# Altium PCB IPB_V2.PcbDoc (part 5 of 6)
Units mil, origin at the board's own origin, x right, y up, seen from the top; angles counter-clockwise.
Board outline 14000 x 12000 mil, 6 copper layers (Top, L2 - Plane/Horiz, L3 - Horiz, L4 - Vert, L5 - Plane/Horiz, Bottom), stack 61.468 mil thick; 657 components, 436 nets, 1897 pads, 873 vias.
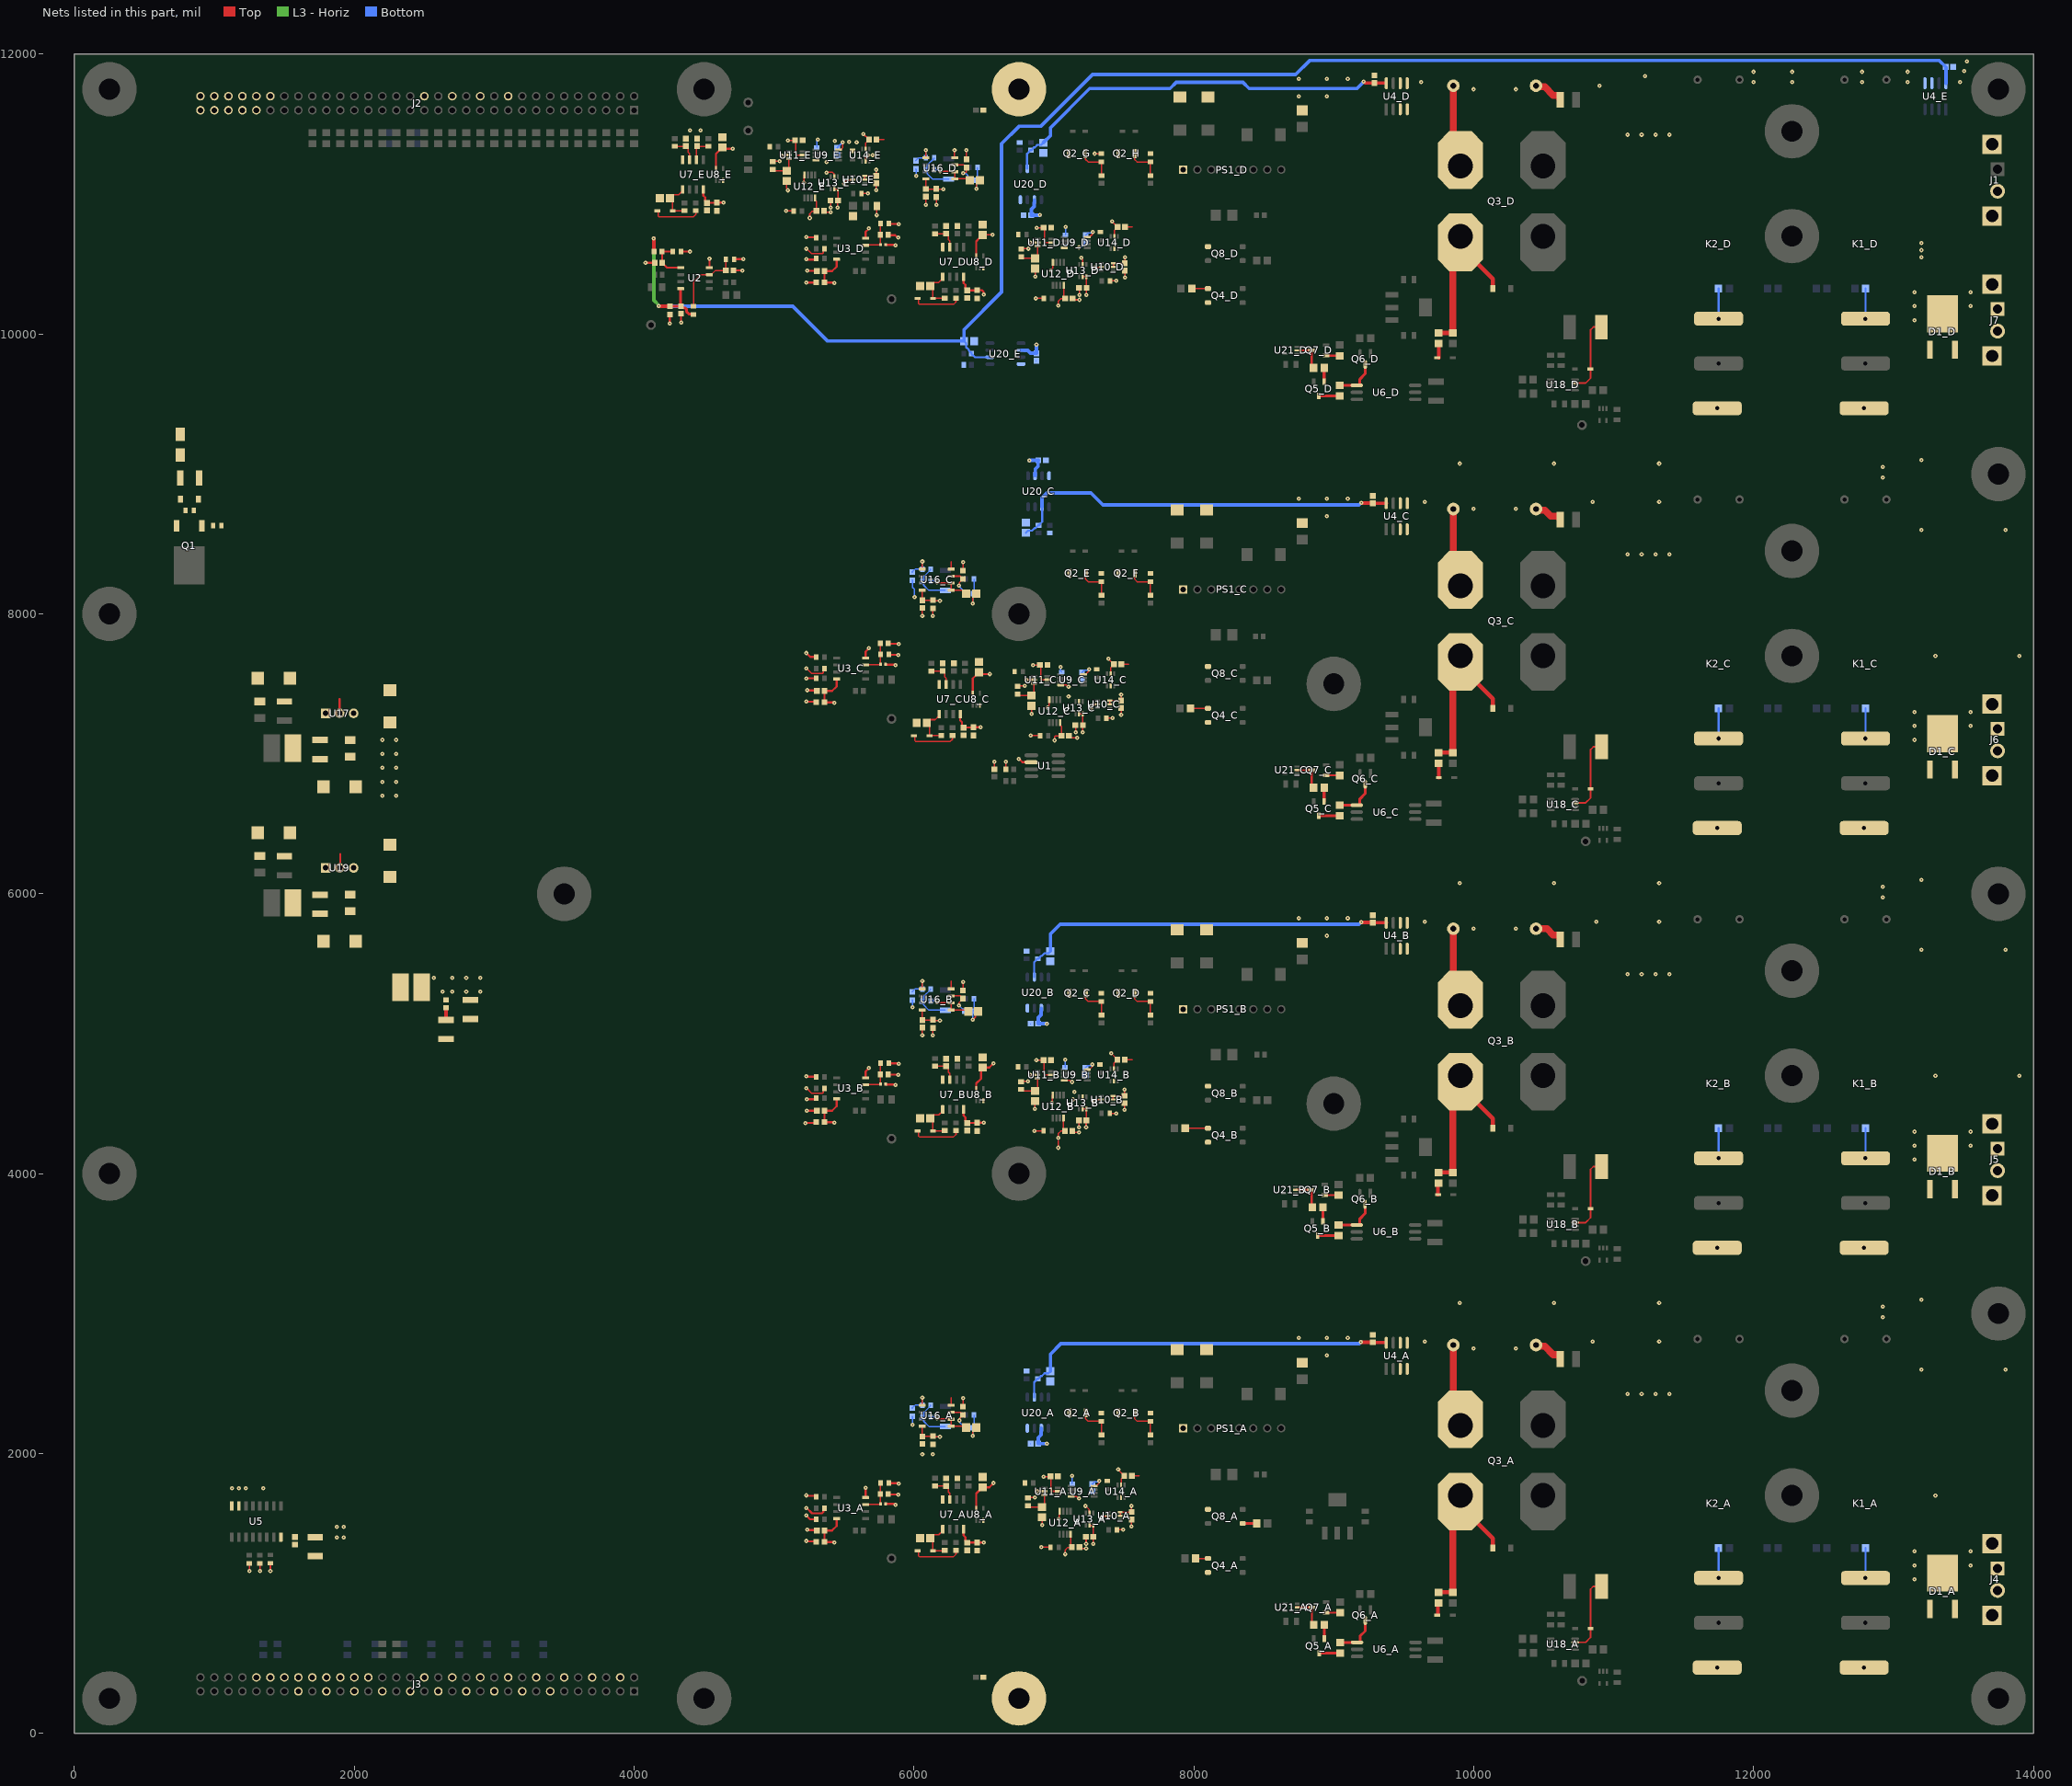
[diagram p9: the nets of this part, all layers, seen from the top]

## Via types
v1: diameter 30, hole 10, Top to Bottom, 873 vias

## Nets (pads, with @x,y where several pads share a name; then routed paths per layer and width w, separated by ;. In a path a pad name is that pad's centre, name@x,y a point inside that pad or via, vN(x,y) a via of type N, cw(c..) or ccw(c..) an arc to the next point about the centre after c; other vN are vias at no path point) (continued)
LV_GND: C1.1 C2.1 C3.2 C4.1 C5.1 C6.2 C7_A.2 C7_B.2 C7_C.2 C7_D.2 C8_A.1 C8_B.1 C8_C.1 C8_D.1 C9_A.1 C9_B.1 C9_C.1 C9_D.1 C10_A.2 C10_B.2 C10_C.2 C10_D.2 C10_E.2 C11.2 C12.1 C14.2 C15.2 C17_A.1 C17_B.1 C17_C.1 C17_D.1 C18_A.1 C18_B.1 C18_C.1 C18_D.1 C20_A.1 C20_B.1 C20_C.1 C20_D.1 C22_A.1 C22_B.1 C22_C.1 C22_D.1 C22_E.1 C23_A.1 C23_B.1 C23_C.1 C23_D.1 C23_E.1 C24_A.2 C24_B.2 C24_C.2 C24_D.2 C24_E.2 C25_A.1 C25_B.1 C25_C.1 C25_D.1 C25_E.1 C26_A.2 C26_B.2 C26_C.2 C26_D.2 C26_E.2 C27_A.1 C27_B.1 C27_C.1 C27_D.1 C27_E.1 C28_A.1 C28_B.1 C28_C.1 C28_D.1 C28_E.1 C29_A.1 C29_B.1 C29_C.1 C29_D.1 C29_E.1 C30_A.1 C30_B.1 C30_C.1 C30_D.1 C30_E.1 C31_A.1 C31_B.1 C31_C.1 C31_D.1 C31_E.1 C32_A.1 C32_B.1 C32_C.1 C32_D.1 C32_E.1 C34_A.1 C34_B.1 C34_C.1 C34_D.1 C34_E.1 C35_A.1 C35_B.1 C35_C.1 C35_D.1 C35_E.1 C36_A.2 C36_B.2 C36_C.2 C36_D.2 C37_A.1 C37_B.1 C37_C.1 C37_D.1 C40_A.1 C40_B.1 C40_C.1 C40_D.1 C41_A.1 C41_B.1 C41_C.1 C41_D.1 C42.2 C43.2 C44.2 C45.1 C46.1 C52.2 C53.2 C54.2 C55.1 C56.1 C57_A.1 C57_B.1 C57_C.1 C57_D.1 C57_E.1 C58_A.1 C58_B.1 C58_C.1 C58_D.1 C58_E.1 J2.20 J2.24 J2.28 J2.32 J2.54 J2.55 J2.57 J2.59 J2.61 J2.63 J3.4 J3.8 J3.12 J3.13 J3.16 J3.17 J3.20 J3.21 J3.24 J3.25 J3.28 J3.29 J3.32 J3.33 J3.37 J3.40 J3.41 J3.44 J3.45 J3.48 J3.49 J3.52 J3.56 PS1_A.1 PS1_B.1 PS1_C.1 PS1_D.1 Q2_A.3 Q2_B.3 Q2_C.3 Q2_D.3 Q2_E.3 Q2_F.3 Q2_G.3 Q2_H.3 Q4_A.2 Q4_B.2 Q4_C.2 Q4_D.2 Q8_A.3 Q8_B.3 Q8_C.3 Q8_D.3 R2.1 R46.1 R50.1 R54_A.1 R54_B.1 R54_C.1 R54_D.1 R56_A.1 R56_B.1 R56_C.1 R56_D.1 R57_A.1 R57_B.1 R57_C.1 R57_D.1 R60.1 R65_A.1 R65_B.1 R65_C.1 R65_D.1 R65_E.1 R65_F.1 R65_G.1 R65_H.1 R70_A.1 R70_B.1 R70_C.1 R70_D.1 R70_E.1 R71_A.1 R71_B.1 R71_C.1 R71_D.1 R71_E.1 R73_A.1 R73_B.1 R73_C.1 R73_D.1 R73_E.1 R74_A.1 R74_B.1 R74_C.1 R74_D.1 R74_E.1 R75_A.1 R75_B.1 R75_C.1 R75_D.1 R75_E.1 R88_A.1 R88_B.1 R88_C.1 R88_D.1 R88_E.1 R95.1 R96.1 R97.1 U2.4 U3_A.4 U3_B.4 U3_C.4 U3_D.4 U4_A.5 U4_A.6 U4_B.5 U4_B.6 U4_C.5 U4_C.6 U4_D.5 U4_D.6 U4_E.5 U4_E.6 U5.7 U5.8 U7_A.4 U7_B.4 U7_C.4 U7_D.4 U7_E.4 U8_A.3 U8_B.3 U8_C.3 U8_D.3 U8_E.3 U9_A.4 U9_B.4 U9_C.4 U9_D.4 U9_E.4 U10_A.2 U10_B.2 U10_C.2 U10_D.2 U10_E.2 U11_A.2 U11_B.2 U11_C.2 U11_D.2 U11_E.2 U12_A.4 U12_B.4 U12_C.4 U12_D.4 U12_E.4 U13_A.2 U13_B.2 U13_C.2 U13_D.2 U13_E.2 U14_A.2 U14_B.2 U14_C.2 U14_D.2 U14_E.2 U16_A.4 U16_B.4 U16_C.4 U16_D.4 U17.2 U19.2 U20_A.4 U20_B.4 U20_C.4 U20_D.4 U20_E.4 | length 7699.3
  Top w10: v1(1250,1160) R95.1@1250,1215 ; v1(1325,1160) R96.1@1325,1215 ; v1(1400,1160.47) R97.1@1400,1215.47 ; v1(5055,11273.55) 5060.41,11273.55 5066.86,11280 U11_E.2@5106.77,11280 ; v1(5084.51,10880) R75_E.1@5150.47,10880 ; C28_E.1@5090,11093.58 5090,11037.71 5097.68,11030.03 v1(5097.68,11027.32) ; v1(5212.2,11080) 5214.41,11082.2 5214.41,11134.49 U12_E.4@5216.61,11136.69 ; U9_E.4@5298.31,11241.61 U9_E.4@5314.06,11241.61 ; C31_E.1@5356.58,10880 5366.58,10870 v1(5405,10870) ; v1(5375.89,11155.12) 5376.79,11156.02 5418.5,11156.02 5427.28,11147.24 5427.28,11126.02 U13_E.2@5430,11123.31 ; C34_E.1@5403.42,10955 5405,10953.42 v1(5405,10905) ; v1(5499.73,11075.33) 5499.73,11079.74 5522.27,11102.28 5558.98,11102.28 U10_E.2@5561.69,11105 ; R73_E.1@5624.53,11005 v1(5670,11005) ; v1(5730,11030) C32_E.1@5730,11078.42 ; C35_E.1@5731.58,11390 5785,11390 ; v1(6060,4987.5) C36_B.2@6060,5043.42 ; v1(6060,7985) C36_C.2@6060,8043.42 ; v1(6085,10925) C36_D.2@6085,10983.42 ; v1(6135,4987.5) C37_B.1@6135,5040.47 ; v1(6135,7985) C37_C.1@6135,8040.47 ; v1(6160,10925) C37_D.1@6160,10980.47 ; 6265,2400 6265,2345.9 U16_A.4@6265.9,2345 ; 6265,5375 6265,5320.9 U16_B.4@6265.9,5320 ; 6265,8375 6265,8320.9 U16_C.4@6265.9,8320 ; v1(6290,11315) 6290,11260.9 U16_D.4@6290.9,11260 ; C40_A.1@6349.21,2334.53 6350,2335.31 v1(6350,2395) ; C40_B.1@6349.21,5309.53 6350,5310.31 v1(6350,5370) ; C40_C.1@6349.21,8309.53 6350,8310.31 v1(6350,8370) ; C40_D.1@6374.21,11249.53 6375,11250.31 v1(6375,11315) ; C1.1@6575,6890 v1(6575,6945) ; v1(6657.02,6942.67) 6657.44,6942.25 R2.1@6657.44,6890 ; v1(6805,7530) U11_C.2@6856.77,7530 ; v1(6830,4705) U11_B.2@6881.77,4705 ; v1(6831.54,10655) U11_D.2@6883.31,10655 ; v1(6834.51,7130) R75_C.1@6900.47,7130 ; v1(6840,7285) C28_C.1@6840,7343.58 ; v1(6859.51,4305) R75_B.1@6925.47,4305 ; v1(6865,4462.5) C28_B.1@6865,4518.58 ; v1(6866.54,10410) C28_D.1@6866.54,10468.58 ; v1(6870,10255) R75_D.1@6927.01,10255 ; v1(6880,1730) U11_A.2@6931.77,1730 ; v1(6909.51,1330) R75_A.1@6975.47,1330 ; v1(6915,1487.5) C28_A.1@6915,1543.58 ; v1(6955,7330) 6955,7335.41 6966.61,7347.03 U12_C.4@6966.61,7386.69 ; v1(6980,10455) 6980,10460.41 6991.67,10472.09 6991.67,10510.22 U12_D.4@6993.15,10511.69 ; v1(6985,4505) 6988.31,4508.31 6988.31,4558.39 U12_B.4@6991.61,4561.69 ; v1(7035,1530) 7038.31,1533.31 7038.31,1583.39 U12_A.4@7041.61,1586.69 ; U9_C.4@7048.31,7491.61 7049,7492.31 7087.91,7492.31 7100.22,7480 v1(7105,7480) ; U9_B.4@7073.31,4666.61 7112.97,4666.61 7124.59,4655 v1(7130,4655) ; U9_D.4@7074.84,10616.61 U9_D.4@7090.59,10616.61 ; C31_C.1@7106.58,7130 7121.58,7115 v1(7165,7115) ; U9_A.4@7123.31,1691.61 7162.97,1691.61 7174.59,1680 v1(7180,1680) ; C31_B.1@7131.58,4305 7141.58,4295 v1(7180,4295) ; C31_D.1@7133.11,10255 7143.11,10245 v1(7181.54,10245) ; C34_C.1@7153.42,7205 7155,7203.42 v1(7155,7155) ; U13_C.2@7178.06,7375.24 U13_C.2@7180,7373.31 ; C34_B.1@7178.42,4380 7180,4378.42 v1(7180,4330) ; C34_D.1@7179.96,10330 7181.54,10328.42 v1(7181.54,10280) ; C31_A.1@7181.57,1330 7191.58,1320 v1(7230,1320) ; v1(7195.62,10545.62) 7195.62,10541.44 7206.54,10530.52 U13_D.2@7206.54,10498.31 ; v1(7225,1625) 7252.28,1597.72 7252.28,1576.02 U13_A.2@7255,1573.31 ; C34_A.1@7228.42,1405 7230,1403.42 v1(7230,1355) ; v1(7268.98,7328.45) 7268.98,7333.5 7287.76,7352.28 7308.98,7352.28 U10_C.2@7311.69,7355 ; v1(7290,4515) 7295.41,4515 7307.7,4527.28 7333.98,4527.28 U10_B.2@7336.69,4530 ; v1(7290,10475) 7292.5,10477.5 7335.73,10477.5 U10_D.2@7338.23,10480 ; v1(7290,11290) 7290.47,11289.53 R65_G.1@7340,11289.53 ; v1(7340,1540) 7345.41,1540 7357.7,1552.28 7383.98,1552.28 U10_A.2@7386.69,1555 ; R73_C.1@7374.53,7255 v1(7420,7255) ; R73_B.1@7399.53,4430 v1(7445,4430) ; R73_D.1@7401.06,10380 v1(7446.53,10380) ; R73_A.1@7449.53,1455 v1(7495,1455) ; v1(7480,7280) C32_C.1@7480,7328.42 ; C35_C.1@7481.58,7640 7535,7640 ; v1(7505,4455) C32_B.1@7505,4503.42 ; v1(7506.54,10405) C32_D.1@7506.54,10453.42 ; C35_B.1@7506.58,4815 7560,4815 ; C35_D.1@7508.11,10765 7561.54,10765 ; v1(7555,1480) C32_A.1@7555,1528.42 ; C35_A.1@7556.57,1840 7610,1840
  Top w15: U17.2@1895,7290 1895,7390 ; U19.2@1899.84,6185 1899.84,6285 ; v1(4081.54,10510) C6.2@4146.85,10510 ; v1(4255,10075.16) C5.1@4255,10140.47 ; R50.1@4332.56,10590 v1(4397.87,10590) ; v1(4335,10081.07) C4.1@4335,10146.38 ; U2.4@4538.35,10475 v1(4538.35,10540.31) ; C3.2@4708.78,10455 v1(4774.09,10455) ; R46.1@4714.69,10535 v1(4780,10535) ; v1(5225,4360) 5227.87,4362.87 5293.34,4362.87 C8_B.1@5300.47,4370 ; v1(5230,1375) 5232.5,1372.5 5297.97,1372.5 C8_A.1@5300.47,1370 ; v1(5230,1557) 5257,1530 R57_A.1@5300.47,1530 ; v1(5230,4695) 5232.5,4692.5 5297.97,4692.5 R56_B.1@5300.47,4690 ; v1(5230,7375) 5232.5,7372.5 5297.97,7372.5 C8_C.1@5300.47,7370 ; v1(5230,7540) 5292.22,7540 5297.97,7534.25 R57_C.1@5297.97,7532.5 ; v1(5230,7721) 5258.44,7692.56 5297.91,7692.56 R56_C.1@5300.47,7690 ; v1(5230,10368) 5231,10369 5299.47,10369 C8_D.1@5300.47,10370 ; v1(5230,10535) 5232.5,10532.5 5297.97,10532.5 R57_D.1@5300.47,10530 ; v1(5230,10695) 5232.5,10692.5 5297.97,10692.5 R56_D.1@5300.47,10690 ; v1(5231.34,1700.66) 5234.21,1697.79 5292.22,1697.79 5292.22,1699.32 5300.47,1691.07 R56_A.1@5300.47,1690 ; v1(5232.5,4532.5) 5297.97,4532.5 R57_B.1@5300.47,4530 ; v1(5235,4450) C7_B.2@5306.38,4450 ; v1(5235.91,1455) 5238.41,1452.5 5303.88,1452.5 C7_A.2@5306.38,1450 ; v1(5235.91,7455) 5238.41,7452.5 5303.88,7452.5 C7_C.2@5306.38,7450 ; v1(5235.91,10455) 5238.41,10452.5 5303.88,10452.5 C7_D.2@5306.38,10450 ; U3_A.4@5653.35,1685 5655,1686.65 v1(5655,1755) ; U3_B.4@5653.35,4685 5653.35,4686.67 5655,4688.33 5655,4730.94 5677.5,4753.44 v1(5677.5,4755) ; U3_C.4@5653.35,7685 5653.35,7686.67 5655,7688.33 5655,7730.94 5677.5,7753.44 v1(5677.5,7755) ; U3_D.4@5653.35,10685 5653.35,10686.67 5655,10688.33 5655,10730.94 5677.5,10753.44 v1(5677.5,10755) ; U14_E.2@5655,11236.69 5655.22,11236.91 5655.22,11263.86 5670,11278.65 v1(5670,11280) ; C9_A.1@5796.06,1640 5855.75,1640 5862.75,1633 v1(5866.53,1633) ; C9_B.1@5796.06,4640 5798.56,4637.5 5864.03,4637.5 v1(5866.53,4635) ; C9_C.1@5796.06,7640 5798.56,7637.5 5864.03,7637.5 v1(5866.53,7635) ; C9_D.1@5796.06,10640 5798.56,10637.5 5864.03,10637.5 v1(5866.53,10635) ; R54_A.1@5815.75,1710 5818.25,1707.5 5883.72,1707.5 v1(5886.22,1705) ; R54_B.1@5815.75,4710 5818.25,4707.5 5883.72,4707.5 v1(5886.22,4705) ; R54_D.1@5815.75,10710 5818.25,10707.5 5864.32,10707.5 5882.16,10689.66 v1(5886.22,10689.66) ; R54_C.1@5819.69,7790 5822.19,7787.5 5887.66,7787.5 v1(5890.16,7785)
  Bottom w8: C57_D.1@6782.09,10850.25 C57_D.1@6783.66,10850.25 ; C57_A.1@6832.09,2070.25 C57_A.1@6833.66,2070.25 ; C57_B.1@6832.09,5072.19 C57_B.1@6833.66,5072.19 ; C57_E.1@6874.88,9807.21 C57_E.1@6874.88,9808.78 ; C57_C.1@6941.57,9097.64 C57_C.1@6943.15,9097.64
  Bottom w10: R70_E.1@5305,11334.53 5305,11378.36 5312.1,11385.46 v1(5312.1,11390.87) ; C41_A.1@5987.75,2265.47 5990,2263.22 v1(5990,2205) ; C41_B.1@5987.75,5240.47 5990,5238.22 v1(5990,5190) ; C41_C.1@5987.75,8240.47 5990,8238.22 5990,8190 6004.05,8175.95 v1(6004.05,8119.7) ; C41_D.1@6012.75,11180.47 6015,11178.22 v1(6015,11130) ; v1(7048.55,7619.96) 7048.55,7590.98 R70_C.1@7055,7584.53 ; R70_B.1@7080,4759.53 v1(7080,4815) ; R70_D.1@7081.54,10709.53 7085,10712.99 v1(7085,10765) ; R70_A.1@7130,1784.53 v1(7130,1840) ; v1(7177.91,10619.52) 7181.74,10623.35 7196.46,10623.35 C29_D.1@7226.54,10653.42
  other v1: 1125,1750 1175,1750 1225,1750 1350,1750 6060,1995.01 6135,1995.01 8950,2700 9650,2800 10850,2800 11325,2800 8750,2825 8950,2825 9100,2825 12925,2975 12925,3050 9900,3075 10575,3075 11325,3075 7135,4530 7145,4585 8950,5700 9650,5800 10875,5800 11325,5800 8750,5825 8950,5825 9100,5825 12925,5975 12925,6050 9900,6075 10575,6075 11325,6075 7105,7410 8950,8700 9650,8800 10850,8800 11325,8800 8750,8825 8950,8825 9100,8825 12925,8975 12925,9050 9900,9075 10575,9075 11325,9075 5375,11230 5705,11280 5590,11370 5535,11375 5435,11380 4400,11456.88 4475,11456.88 8750,11700 8950,11700 10900,11775 9625,11800 12000,11800 12275,11800 12775,11800 13100,11800 13475,11800 8750,11825 8950,11825 9100,11825 11225,11842.5 12000,11875 12275,11875 12775,11875 13100,11875 13505,11880 13525,11950
LV_IGB_P24V: D2.1 J2.56 J2.58 J2.60 J2.62 J2.64
LV_ISNS_P5V: C4.2 C5.2 C10_E.1 C58_E.2 R44.1 R48.1 R87_E.2 U2.8 U4_E.8 U20_E.6 | length 12196.2
  Top w10: C4.2@4331.65,10202.87 C4.2@4335,10199.53
  Top w20: C5.2@4255,10199.53 C4.2@4335,10199.53 4345.67,10188.86 4355.58,10188.86 4357.39,10187.05 4363.95,10187.05 4375.67,10175.33 4375.67,10158.86 4390.6,10143.93 4421.54,10143.93 R44.1@4425,10140.47 ; C4.2@4331.65,10202.87 U2.8@4331.65,10325
  Top w25: v1(4140,10685) 4140.47,10684.53 4140.47,10590.47 R48.1@4140.94,10590 ; v1(4175,10200) 4175.24,10199.76 4254.76,10199.76 C5.2@4255,10199.53
  L3 - Horiz w25: v1(4140,10685) 4140,10241.76 4175,10206.76 v1(4175,10200)
  Bottom w15: C58_E.2@6357.24,9950.36 6372.47,9935.12 6372.47,9907.12 6391.32,9888.28 6391.32,9882.31 6400.1,9873.53 6401,9873.53 6411.22,9863.31 6411.22,9855.83 6416.43,9850.62 6419.39,9850.62 6436.22,9833.78 U20_E.6@6542.44,9833.78
  Bottom w25: v1(4175,10200) 5133.95,10200 5383.6,9950.36 C58_E.2@6357.24,9950.36 6357.24,10032.24 6625,10300 6625,11360.36 6749.64,11485 6905,11485 7275,11855 8726.97,11855 8826.97,11955 13328.43,11955 C10_E.1@13373.43,11910 ; C10_E.1@13374.65,11905.36 13374.65,11793.41 U4_E.8@13375,11793.06
LV_ISNS_P12V: C14.1 C57_A.2 C57_B.2 C57_C.2 C57_D.2 C57_E.2 L1.2 R59.2 U20_A.2 U20_B.2 U20_C.2 U20_D.2 U20_E.2 | length 893.8
  Bottom w25: U20_E.2@6764.88,9885.09 6765.04,9885.25 6784.84,9885.25 6786.3,9883.78 6812.45,9883.78 6832.4,9863.83 C57_E.2@6871.4,9863.83 ; v1(6825.24,9097.88) 6825.36,9097.76 6888.3,9097.76 C57_C.2@6888.43,9097.64 ; C57_D.2@6836.81,10850.25 6836.93,10850.12 6899.88,10850.12 v1(6900,10850) ; C57_D.2@6838.71,10853.72 6838.71,10892.72 6858.66,10912.67 6858.66,10938.83 6860.12,10940.29 6860.12,10960.09 U20_D.2@6859.96,10960.25 ; U20_C.2@6865.27,8987.64 6865.11,8987.8 6865.11,9007.6 6866.57,9009.06 6866.57,9035.21 6886.53,9055.17 C57_C.2@6886.53,9094.17 ; C57_E.2@6874.88,9861.93 6875,9862.06 6875,9925 v1(6875.12,9925.12) ; C57_A.2@6886.81,2070.25 6886.93,2070.12 6949.88,2070.12 v1(6950,2070) ; C57_B.2@6886.81,5072.19 6886.93,5072.07 6949.88,5072.07 v1(6950,5071.94) ; C57_A.2@6888.71,2073.72 6888.71,2112.72 6908.66,2132.67 6908.66,2158.83 6910.12,2160.29 6910.12,2180.09 U20_A.2@6909.96,2180.25 ; C57_B.2@6888.71,5075.66 6888.71,5114.66 6908.66,5134.61 6908.66,5160.77 6910.12,5162.23 6910.12,5182.03 U20_B.2@6909.96,5182.19
  other v1: 2632,5300 2700,5300 2800,5300 2900,5300 2568,5400 2700,5400 2800,5400 2900,5400
LV_P5V: C7_A.1 C7_B.1 C7_C.1 C7_D.1 C8_A.2 C8_B.2 C8_C.2 C8_D.2 C11.1 C12.2 C22_A.2 C22_B.2 C22_C.2 C22_D.2 C22_E.2 C23_A.2 C23_B.2 C23_C.2 C23_D.2 C23_E.2 C27_A.2 C27_B.2 C27_C.2 C27_D.2 C27_E.2 C29_A.2 C29_B.2 C29_C.2 C29_D.2 C29_E.2 C30_A.2 C30_B.2 C30_C.2 C30_D.2 C30_E.2 C31_A.2 C31_B.2 C31_C.2 C31_D.2 C31_E.2 C32_A.2 C32_B.2 C32_C.2 C32_D.2 C32_E.2 C34_A.2 C34_B.2 C34_C.2 C34_D.2 C34_E.2 C35_A.2 C35_B.2 C35_C.2 C35_D.2 C35_E.2 C36_A.1 C36_B.1 C36_C.1 C36_D.1 C37_A.2 C37_B.2 C37_C.2 C37_D.2 C42.1 R42.2 R52_A.2 R52_B.2 R52_C.2 R52_D.2 R55_A.1 R55_B.1 R55_C.1 R55_D.1 R72_A.2 R72_B.2 R72_C.2 R72_D.2 R72_E.2 U1.2 U3_A.8 U3_B.8 U3_C.8 U3_D.8 U5.16 U7_A.8 U7_B.8 U7_C.8 U7_D.8 U7_E.8 U8_A.5 U8_B.5 U8_C.5 U8_D.5 U8_E.5 U9_A.8 U9_B.8 U9_C.8 U9_D.8 U9_E.8 U10_A.5 U10_A.6 U10_B.5 U10_B.6 U10_C.5 U10_C.6 U10_D.5 U10_D.6 U10_E.5 U10_E.6 U11_A.5 U11_B.5 U11_C.5 U11_D.5 U11_E.5 U12_A.8 U12_B.8 U12_C.8 U12_D.8 U12_E.8 U13_A.5 U13_A.6 U13_B.5 U13_B.6 U13_C.5 U13_C.6 U13_D.5 U13_D.6 U13_E.5 U13_E.6 U14_A.5 U14_B.5 U14_C.5 U14_D.5 U14_E.5 U16_A.8 U16_B.8 U16_C.8 U16_D.8 U17.3 | length 10693.6
  Top w10: R72_E.2@4990,11232.56 4992.44,11235 v1(5040,11235) ; v1(5100,11385) 5149.43,11385 C30_E.2@5150.43,11386 5155,11381.43 5155,11286 5161,11280 U11_E.5@5203.23,11280 ; v1@5233.41,4610 5268.41,4575 5344.68,4575 5351.28,4581.6 5351.28,4601.75 R55_B.1@5359.53,4610 ; v1@5233.41,7610 5268.41,7575 5344.68,7575 5351.28,7581.6 5351.28,7601.75 R55_C.1@5359.53,7610 ; v1@5233.41,10610 5268.41,10575 5344.68,10575 5351.28,10581.6 5351.28,10601.75 R55_D.1@5359.53,10610 ; v1(5255,10830) 5255,10860 5273.61,10878.61 C31_E.2@5302.04,10878.61 ; U12_E.8@5293.39,10973.31 5293.39,10957.56 5297.24,10953.7 5297.57,10953.7 5303.43,10947.84 C31_E.2@5303.43,10880 ; U13_E.5@5430,11036.69 U13_E.6@5455.59,11036.69 5455.59,10955.98 C34_E.2@5456.57,10955 5455,10953.43 v1(5455,10905) ; U9_E.8@5461.69,11318.39 5477.44,11318.39 5491.35,11332.3 v1@5491.35,11371.91 ; v1(5638.07,11430.35) C35_E.2@5678.43,11390 5655,11366.57 U14_E.5@5655,11323.31 ; U10_E.5@5648.31,11105 U10_E.6@5648.31,11130.59 5729.02,11130.59 C32_E.2@5730,11131.57 v1(5730,11175) ; v1(5734.27,10849.83) 5734.37,10849.83 R42.2@5734.37,10915 ; U16_A.8@6059.21,2195 6059.21,2122.36 C36_A.1@6060,2121.57 C37_A.2@6132.05,2121.57 ; U16_B.8@6059.21,5170 6059.21,5097.36 C36_B.1@6060,5096.57 C37_B.2@6132.05,5096.57 ; U16_C.8@6059.21,8170 6059.21,8097.36 C36_C.1@6060,8096.57 C37_C.2@6132.05,8096.57 ; U16_D.8@6084.21,11110 6084.21,11037.36 C36_D.1@6085,11036.57 C37_D.2@6157.05,11036.57 ; C37_A.2@6135,2124.53 6139.53,2120 v1(6185,2120) ; C37_B.2@6135,5099.53 6139.53,5095 v1(6185,5095) ; C37_C.2@6135,8099.53 6139.53,8095 v1(6185,8095) ; C37_D.2@6160,11039.53 6164.53,11035 v1(6210,11035) ; C27_D.2@6490.49,10708.58 6491.91,10710 v1(6560,10710) ; R72_C.2@6740,7482.56 6742.44,7485 v1(6790,7485) ; R72_B.2@6765,4657.56 6767.44,4660 v1(6815,4660) ; R72_D.2@6766.54,10607.56 6768.98,10610 v1(6816.54,10610) ; R72_A.2@6815,1682.56 6817.44,1685 v1(6865,1685) ; v1(6850,7635) 6899.43,7635 C30_C.2@6900.43,7636 6905,7631.43 6905,7536 6911,7530 U11_C.5@6953.23,7530 ; v1(6875,4810) 6924.43,4810 C30_B.2@6925.43,4811 6930,4806.43 6930,4711 6936,4705 U11_B.5@6978.23,4705 ; v1(6876.54,10760) 6925.96,10760 C30_D.2@6926.96,10761 6931.54,10756.43 6931.54,10661 6937.54,10655 U11_D.5@6979.76,10655 ; v1(6925,1835) 6974.43,1835 C30_A.2@6975.43,1836 6980,1831.43 6980,1736 6986,1730 U11_A.5@7028.23,1730 ; v1(7005,7096.75) 7005,7122.76 7010.86,7128.61 C31_C.2@7052.04,7128.61 ; v1(7030,4185) 7030,4235 ; v1(7030,4255) 7030,4285 7048.61,4303.61 7077.04,4303.61 C31_B.2@7078.43,4305 7068.39,4315.04 U12_B.8@7068.39,4398.31 ; v1(7031.54,10205) 7031.54,10235 7050.15,10253.61 C31_D.2@7078.57,10253.61 ; U12_C.8@7043.39,7223.31 7043.39,7207.56 7047.24,7203.7 7047.57,7203.7 7053.43,7197.84 C31_C.2@7053.43,7130 ; U12_D.8@7069.92,10348.31 7069.92,10265.04 C31_D.2@7079.96,10255 ; v1(7080,1280) 7080,1310 7098.61,1328.61 7127.04,1328.61 C31_A.2@7128.43,1330 7118.39,1340.04 U12_A.8@7118.39,1423.31 ; U13_C.5@7180,7286.69 U13_C.6@7205.59,7286.69 7205.59,7205.98 C34_C.2@7206.57,7205 7205,7203.43 v1(7205,7155) ; U13_B.5@7205,4461.69 U13_B.6@7230.59,4461.69 7230.59,4380.98 C34_B.2@7231.57,4380 7230,4378.43 v1(7230,4330) ; U13_D.5@7206.54,10411.69 U13_D.6@7232.13,10411.69 7232.13,10330.98 C34_D.2@7233.11,10330 7231.54,10328.43 v1(7231.54,10280) ; U9_C.8@7211.69,7568.39 7227.44,7568.39 7248.09,7589.03 7248.09,7603.09 v1(7250,7605) ; U9_B.8@7236.69,4743.39 7252.44,4743.39 7273.09,4764.03 7273.09,4778.09 v1(7275,4780) ; U9_D.8@7238.23,10693.39 7253.98,10693.39 7274.62,10714.03 7274.62,10728.09 v1(7276.54,10730) ; U13_A.5@7255,1486.69 U13_A.6@7280.59,1486.69 7280.59,1405.98 C34_A.2@7281.57,1405 7280,1403.43 v1(7280,1355) ; U9_A.8@7286.69,1768.39 7302.44,1768.39 7323.09,1789.03 7323.09,1803.09 v1(7325,1805) ; v1@7388.07,7680.35 C35_C.2@7428.43,7640 7405,7616.57 U14_C.5@7405,7573.31 ; U10_C.5@7398.31,7355 U10_C.6@7398.31,7380.59 7479.02,7380.59 C32_C.2@7480,7381.57 v1(7480,7425) ; v1(7410,4860) 7410,4858.43 C35_B.2@7453.43,4815 7430,4791.57 U14_B.5@7430,4748.31 ; v1@7414.61,10805.35 C35_D.2@7454.96,10765 7431.54,10741.57 U14_D.5@7431.54,10698.31 ; U10_B.5@7423.31,4530 U10_B.6@7423.31,4555.59 7504.02,4555.59 C32_B.2@7505,4556.57 v1(7505,4600) ; U10_D.5@7424.84,10480 U10_D.6@7424.84,10505.59 7505.55,10505.59 C32_D.2@7506.54,10506.57 v1(7506.54,10550) ; v1(7460,1885) 7460,1883.43 C35_A.2@7503.43,1840 7480,1816.57 U14_A.5@7480,1773.31 ; U10_A.5@7473.31,1555 U10_A.6@7473.31,1580.59 7554.02,1580.59 C32_A.2@7555,1581.57 v1(7555,1625)
  Top w15: U7_E.8@4495,11036.65 4495,10989.55 4507.81,10976.73 4507.81,10951.71 4521.48,10938.05 4588.52,10938.05 C23_E.2@4590,10936.57 ; U8_E.5@4584.41,11175.47 4584.41,11287.99 4607.97,11311.55 4607.97,11312.54 4629.02,11333.58 C27_E.2@4630,11333.58 4630,11325 v1(4705,11325) ; C23_E.2@4590,10939.53 v1@4639.53,10939.53 ; v1(5230,1610) 5233.41,1610 5270.6,1572.82 5342.49,1572.82 5351.28,1581.6 5351.28,1601.75 R55_A.1@5359.53,1610 ; v1(5230,4610) v1@5233.41,4610 ; v1(5230,7610) v1@5233.41,7610 ; v1(5230,10610) v1@5233.41,10610 ; v1(5430,1365) 5427.5,1367.5 5362.03,1367.5 C8_A.2@5359.53,1370 C7_A.1@5359.53,1450 5415,1450 5446.65,1481.65 U3_A.8@5446.65,1535 ; v1(5430,4365) 5427.5,4367.5 5362.03,4367.5 C8_B.2@5359.53,4370 C7_B.1@5359.53,4450 5415,4450 5446.65,4481.65 U3_B.8@5446.65,4535 ; v1(5430,7365) 5427.5,7367.5 5362.03,7367.5 C8_C.2@5359.53,7370 C7_C.1@5359.53,7450 5415,7450 5446.65,7481.65 U3_C.8@5446.65,7535 ; v1(5430,10365) 5427.5,10367.5 5362.03,10367.5 C8_D.2@5359.53,10370 C7_D.1@5359.53,10450 5415,10450 5446.65,10481.65 U3_D.8@5446.65,10535 ; R52_C.2@5815.75,7710 5818.25,7707.5 5883.72,7707.5 v1(5886.22,7705) ; R52_A.2@5819.69,1790 5822.19,1787.5 5887.66,1787.5 v1(5890.16,1785) ; R52_B.2@5819.69,4790 5822.19,4787.5 5887.66,4787.5 v1(5890.16,4785) ; R52_D.2@5819.69,10790 5822.19,10787.5 5887.66,10787.5 v1(5890.16,10785) ; U7_C.8@6330,7286.65 6330,7239.55 6342.81,7226.73 6342.81,7201.71 6356.48,7188.05 6423.52,7188.05 C23_C.2@6425,7186.57 ; U7_A.8@6355,1461.65 6355,1414.55 6367.81,1401.73 6367.81,1376.71 6381.48,1363.05 C23_A.2@6448.52,1363.05 ; U7_B.8@6355,4461.65 6355,4414.55 6367.81,4401.73 6367.81,4376.71 6381.48,4363.05 C23_B.2@6448.52,4363.05 ; U7_D.8@6355,10411.65 6355,10364.55 6367.81,10351.73 6367.81,10326.71 6381.48,10313.05 C23_D.2@6448.52,10313.05 ; U8_C.5@6419.41,7425.47 6419.41,7537.99 6442.97,7561.55 6442.97,7562.54 6464.02,7583.58 C27_C.2@6465,7583.58 ; C23_C.2@6425,7189.53 v1@6474.53,7189.53 ; U8_A.5@6444.41,1600.47 6444.41,1712.99 6467.97,1736.55 6467.97,1737.54 6489.02,1758.58 C27_A.2@6490,1758.58 6538.22,1758.58 v1(6568.67,1789.03) ; U8_B.5@6444.41,4600.47 6444.41,4644.41 6480,4680 6480,4749.57 6489.02,4758.58 6538.22,4758.58 v1(6568.67,4789.03) ; U8_D.5@6444.41,10550.47 6444.41,10662.99 6467.97,10686.55 6467.97,10687.54 6485.46,10705.03 6489.02,10708.58 C27_D.2@6490,10708.58 ; C23_A.2@6450,1364.53 6499.53,1364.53 v1(6500,1365) ; C23_B.2@6450,4364.53 6499.53,4364.53 v1(6500,4365) ; C23_D.2@6450,10314.53 6484.53,10314.53 6497.13,10301.93 6497.13,10285.37 v1(6500,10282.5) ; C27_C.2@6465.49,7578.66 6465.49,7570.08 v1(6540.49,7570.08) ; v1(6750,6965) 6775,6940 U1.2@6838.54,6940
  Bottom w10: C29_E.2@5450,11331.57 5469.14,11350.72 5470.12,11350.72 v1(5491.34,11371.93) ; C29_C.2@7200,7581.57 7215.67,7597.24 7239.54,7597.24 7247.29,7605 v1(7250,7605) ; C29_B.2@7225,4756.57 7240.67,4772.24 7264.54,4772.24 7272.29,4780 v1(7275,4780) ; C29_D.2@7226.54,10706.57 7242.2,10722.24 7266.07,10722.24 7273.83,10730 v1(7276.54,10730) ; C29_A.2@7275,1781.57 7290.67,1797.24 7314.54,1797.24 7322.29,1805 v1(7325,1805)
  other v1: 1875,1400 1925,1400 1875,1475 1925,1475 2200,6700 2300,6700 2200,6800 2300,6800 2200,6900 2300,6900 2200,7000 2300,7000 2200,7100 2300,7100 6475,7190 7388.07,7681.34 7414.61,10806.34 4640,10940
LV_P12V: C52.1 L1.1 U19.3
MT1_2: J1.MT1
MT2_2: J1.MT2
MT_1_9: J4.MT1
MT_2_9: J4.MT2
MT_3_9: J5.MT1
MT_4_9: J5.MT2
MT_5_9: J6.MT1
MT_6_9: J6.MT2
MT_7_9: J7.MT1
MT_8_9: J7.MT2
MVC_L_CURRENT_3: J3.46
MVC_L_VOLTAGE_3: J3.54
MVC_R_CURRENT_3: J3.42
MVC_R_VOLTAGE_3: J3.50
N187: J1.B K2_A.1 K2_B.1 K2_C.1 K2_D.1 R103_A.1 R103_B.1 R103_C.1 R103_D.1 | length 860
  Bottom w15: K2_A.1@11750,1110 R103_A.1@11750,1325 ; K2_B.1@11750,4110 R103_B.1@11750,4325 ; K2_C.1@11750,7110 R103_C.1@11750,7325 ; K2_D.1@11750,10110 R103_D.1@11750,10325
  other v1: 13300,1700 11100,2425 11200,2425 11300,2425 11400,2425 13200,2600 13800,2600 10000,2750 10300,2750 13200,3100 13300,4700 13900,4700 11100,5425 11200,5425 11300,5425 11400,5425 13200,5600 13800,5600 10000,5750 10300,5750 13200,6100 13300,7700 13900,7700 11100,8425 11200,8425 11300,8425 11400,8425 13200,8600 13800,8600 10000,8750 10300,8750 13200,9100 13200,10550 13200,10600 13200,10650 11100,11425 11200,11425 11300,11425 11400,11425 10000,11750 10300,11750
NetC3_1: C3.1 R44.2 R46.2 U2.3 | length 519.2
  Top w10: R44.2@4425,10199.53 4425,10375 4475,10425 U2.3@4538.35,10425 4552.13,10425 4582.13,10455 C3.1@4655.63,10455 R46.2@4655.63,10535
NetC6_1: C6.1 R48.2 R50.2 U2.5 | length 303.6
  Top w15: R50.2@4277.44,10590 4200,10590 C6.1@4200,10510 4235,10475 U2.5@4331.65,10475
NetC9_A_2: C9_A.2 R52_A.1 R54_A.2 U3_A.3 | length 259.4
  Top w10: U3_A.3@5653.35,1635 5655.85,1637.5 5758.13,1637.5 C9_A.2@5760.63,1640 R54_A.2@5760.63,1710 R52_A.1@5760.63,1790
NetC9_B_2: C9_B.2 R52_B.1 R54_B.2 U3_B.3 | length 259.4
  Top w10: U3_B.3@5653.35,4635 5655.85,4637.5 5758.13,4637.5 C9_B.2@5760.63,4640 R54_B.2@5760.63,4710 R52_B.1@5760.63,4790
NetC9_C_2: C9_C.2 R52_C.1 R54_C.2 U3_C.3 | length 259.4
  Top w10: U3_C.3@5653.35,7635 5655.85,7637.5 5758.13,7637.5 C9_C.2@5760.63,7640 R52_C.1@5760.63,7710 R54_C.2@5760.63,7790
NetC9_D_2: C9_D.2 R52_D.1 R54_D.2 U3_D.3 | length 259.4
  Top w10: U3_D.3@5653.35,10635 5655.85,10637.5 5758.13,10637.5 C9_D.2@5760.63,10640 R54_D.2@5760.63,10710 R52_D.1@5760.63,10790
NetC10_A_1: C10_A.1 C58_A.2 R87_A.2 U4_A.8 U20_A.6 | length 2816.5
  Top w25: v1(9194.33,2795.89) 9195.56,2794.66 C10_A.1@9278.77,2794.66 9280.18,2793.24 9374.82,2793.24 U4_A.8@9375,2793.06
  Bottom w15: U20_A.6@6858.66,2402.69 6858.66,2508.91 6875.49,2525.74 6875.49,2528.69 6880.71,2533.91 6888.19,2533.91 6898.41,2544.12 6898.41,2545.02 6907.19,2553.81 6913.15,2553.81 6932,2572.65 6960,2572.65 C58_A.2@6975.24,2587.88
  Bottom w25: C58_A.2@6975.24,2587.88 6975.24,2710.24 7050,2785 9182.08,2785 9192.98,2795.89 v1(9194.33,2795.89)
NetC10_B_1: C10_B.1 C58_B.2 R87_B.2 U4_B.8 U20_B.6 | length 2815
  Top w25: v1@9194.33,5797.84 v1@9195.56,5796.6 ; v1@9197.14,5794.66 C10_B.1@9280.34,5794.66 ; C10_B.1@9281.76,5793.24 U4_B.8@9376.39,5793.24
  Bottom w15: U20_B.6@6858.66,5404.63 6858.66,5510.85 6875.49,5527.68 6875.49,5530.63 6880.71,5535.85 6888.19,5535.85 6898.41,5546.06 6898.41,5546.96 6907.19,5555.75 6913.15,5555.75 6932,5574.59 6960,5574.59 C58_B.2@6975.24,5589.83
  Bottom w25: C58_B.2@6975.24,5589.83 6975.24,5712.18 7044.79,5781.73 9180.39,5781.73 9194.55,5795.89 v1(9195.9,5795.89)
NetC10_C_1: C10_C.1 C58_C.2 R87_C.2 U4_C.8 U20_C.6 | length 2835.6
  Top w25: v1@9197.14,8792.72 C10_C.1@9280.34,8792.72 ; C10_C.1@9281.76,8791.3 U4_C.8@9376.39,8791.3
  Bottom w15: C58_C.2@6800,8580 6815.23,8595.24 6843.24,8595.24 6862.08,8614.08 6868.04,8614.08 6876.83,8622.86 6876.83,8623.76 6887.05,8633.98 R87_C.2@6890,8633.98 6894.53,8633.98 6899.74,8639.19 6899.74,8642.15 6916.57,8658.98 U20_C.6@6916.57,8765.2
  Bottom w25: U20_C.6@6915,8765.2 6915,8830 6950,8865 7265,8865 7350.21,8779.79 9180.39,8779.79 v1@9194.55,8793.95
  other v1: 9195.9,8793.95
NetC10_D_1: C10_D.1 C58_D.2 R87_D.2 U4_D.8 U20_D.6 | length 2963.3
  Top w25: v1(9213.43,11803.06) 9214.78,11803.06 9222.83,11795 C10_D.1@9290,11795 9373.96,11795 9375,11793.96 U4_D.8@9375,11793.06
  Bottom w15: U20_D.6@6808.66,11182.69 6808.66,11288.91 6825.49,11305.74 6825.49,11308.69 6830.71,11313.91 R87_D.2@6835.24,11313.91 6838.19,11313.91 6848.41,11324.12 6848.41,11325.02 6857.19,11333.81 6863.15,11333.81 6882,11352.65 6910,11352.65 C58_D.2@6925.24,11367.88
  Bottom w25: C58_D.2@6925.24,11367.88 6975.24,11417.88 6975.24,11475.24 7255,11755 7830,11755 7875,11800 8350,11800 8395,11755 9165.37,11755 v1(9213.43,11803.06)
NetC13_1: C13.1 D3.2 Q1.1 R58.1 R60.2
NetC13_2: C13.2 D2.2 D3.1 Q1.3 R58.2
NetC15_1: C15.1 R59.1 | length 88
  Top w25: C15.1@2655,5098.23 R59.1@2655,5186.22
NetC24_E_1: C24_E.1 R66_E.2 U7_E.2 | length 182.6
  Top w10: U7_E.2@4445,11243.35 4445,11338.43 C24_E.1@4450,11343.43 4450.98,11342.44 R66_E.2@4530,11342.44
NetC25_A_2: C25_A.2 D5_A.1 R68_A.1 U7_A.5 | length 308.5
  Top w10: U7_A.5@6205,1461.65 6205,1447.87 6176.65,1419.53 6139.96,1419.53 6116.42,1395.98 C25_A.2@6116.42,1395 6135.12,1376.3 D5_A.1@6135.12,1305 6217.56,1305 R68_A.1@6220,1307.44
NetC25_B_2: C25_B.2 D5_B.1 R68_B.1 U7_B.5 | length 308.5
  Top w10: U7_B.5@6205,4461.65 6205,4447.87 6176.65,4419.53 6139.96,4419.53 6116.42,4395.98 C25_B.2@6116.42,4395 6135.12,4376.3 D5_B.1@6135.12,4305 6217.56,4305 R68_B.1@6220,4307.44
NetC25_C_2: C25_C.2 D5_C.1 R68_C.1 U7_C.5 | length 308.5
  Top w10: U7_C.5@6180,7286.65 6180,7272.87 6151.65,7244.53 6114.96,7244.53 6091.42,7220.98 C25_C.2@6091.42,7220 6110.12,7201.3 D5_C.1@6110.12,7130 6192.56,7130 R68_C.1@6195,7132.44
NetC25_D_2: C25_D.2 D5_D.1 R68_D.1 U7_D.5 | length 308.5
  Top w10: U7_D.5@6205,10411.65 6205,10397.87 6176.65,10369.53 6139.96,10369.53 6116.42,10345.98 C25_D.2@6116.42,10345 6135.12,10326.3 D5_D.1@6135.12,10255 6217.56,10255 R68_D.1@6220,10257.44
NetC25_E_2: C25_E.2 D5_E.1 R68_E.1 U7_E.5 | length 308.5
  Top w10: U7_E.5@4345,11036.65 4345,11022.87 4316.65,10994.53 4279.96,10994.53 4256.42,10970.98 C25_E.2@4256.42,10970 4275.12,10951.3 D5_E.1@4275.12,10880 4357.56,10880 R68_E.1@4360,10882.44
NetC26_A_1: C26_A.1 R69_A.2 U7_A.3 | length 190.8
  Top w10: R69_A.2@6150,1767.44 6229.02,1767.44 C26_A.1@6230,1768.43 6245.67,1752.76 6245.67,1725.02 6255,1715.69 U7_A.3@6255,1668.35
NetC26_B_1: C26_B.1 R69_B.2 U7_B.3 | length 190.8
  Top w10: R69_B.2@6150,4767.44 6229.02,4767.44 C26_B.1@6230,4768.43 6245.67,4752.76 6245.67,4725.02 6255,4715.69 U7_B.3@6255,4668.35
NetC26_C_1: C26_C.1 R69_C.2 U7_C.3 | length 190.8
  Top w10: R69_C.2@6125,7592.44 6204.02,7592.44 C26_C.1@6205,7593.43 6220.67,7577.76 6220.67,7550.02 6230,7540.69 U7_C.3@6230,7493.35
NetC26_D_1: C26_D.1 R69_D.2 U7_D.3 | length 190.8
  Top w10: R69_D.2@6150,10717.44 6229.02,10717.44 C26_D.1@6230,10718.43 6245.67,10702.76 6245.67,10675.02 6255,10665.69 U7_D.3@6255,10618.35
NetC26_E_1: C26_E.1 R69_E.2 U7_E.3 | length 190.8
  Top w10: R69_E.2@4290,11342.44 4369.02,11342.44 C26_E.1@4370,11343.43 4385.67,11327.76 4385.67,11300.02 4395,11290.69 U7_E.3@4395,11243.35
NetC28_A_2: C28_A.2 R72_A.1 U11_A.3 | length 199.5
  Top w10: R72_A.1@6815,1627.44 6826.02,1616.42 C28_A.2@6915,1616.42 6931.77,1633.19 U11_A.3@6931.77,1704.41
NetC28_B_2: C28_B.2 R72_B.1 U11_B.3 | length 199.5
  Top w10: R72_B.1@6765,4602.44 6776.02,4591.42 C28_B.2@6865,4591.42 6881.77,4608.19 U11_B.3@6881.77,4679.41
NetC28_C_2: C28_C.2 R72_C.1 U11_C.3 | length 199.5
  Top w10: R72_C.1@6740,7427.44 6751.02,7416.42 C28_C.2@6840,7416.42 6856.77,7433.19 U11_C.3@6856.77,7504.41
NetC28_D_2: C28_D.2 R72_D.1 U11_D.3 | length 199.5
  Top w10: R72_D.1@6766.54,10552.44 6777.56,10541.42 C28_D.2@6866.54,10541.42 6883.31,10558.19 U11_D.3@6883.31,10629.41
NetC28_E_2: C28_E.2 R72_E.1 U11_E.3 | length 199.5
  Top w10: R72_E.1@4990,11177.44 5001.02,11166.42 C28_E.2@5090,11166.42 5106.77,11183.19 U11_E.3@5106.77,11254.41
NetC38_A_2: C38_A.2 R77_A.2 R78_A.1 | length 316.2
  Bottom w10: R77_A.2@6059.68,2255.34 6070,2265.66 6070,2292.32 6118.74,2341.06 R78_A.1@6118.74,2345 ; R77_A.2@6059.68,2259.28 6068.52,2250.44 6068.52,2231.48 6106.85,2193.15 C38_A.2@6223.28,2193.15
NetC38_B_2: C38_B.2 R77_B.2 R78_B.1 | length 316.2
  Bottom w10: R77_B.2@6059.68,5230.34 6070,5240.66 6070,5267.32 6118.74,5316.06 R78_B.1@6118.74,5320 ; R77_B.2@6059.68,5234.28 6068.52,5225.44 6068.52,5206.48 6106.85,5168.15 C38_B.2@6223.28,5168.15
NetC38_C_2: C38_C.2 R77_C.2 R78_C.1 | length 316.2
  Bottom w10: R77_C.2@6059.68,8230.34 6070,8240.66 6070,8267.32 6118.74,8316.06 R78_C.1@6118.74,8320 ; R77_C.2@6059.68,8234.28 6068.52,8225.44 6068.52,8206.48 6106.85,8168.15 C38_C.2@6223.28,8168.15
NetC38_D_2: C38_D.2 R77_D.2 R78_D.1 | length 316.2
  Bottom w10: R77_D.2@6084.68,11170.34 6095,11180.66 6095,11207.32 6143.74,11256.06 R78_D.1@6143.74,11260 ; R77_D.2@6084.68,11174.28 6093.52,11165.44 6093.52,11146.48 6131.85,11108.15 C38_D.2@6248.28,11108.15
NetC39_A_1: C39_A.1 R79_A.2 R80_A.1 | length 224.6
  Top w10: v1(6420,2125) 6420.12,2125.12 6420.12,2160.47 C39_A.1@6444.65,2185
  Bottom w10: v1(6420,2125) 6420,2184.06 R80_A.1@6419.06,2185 6428.74,2194.68 R79_A.2@6428.74,2275
NetC39_A_2: C39_A.2 R77_A.1 U16_A.1 U16_A.2 | length 315.7
  Top w10: v1(6162.56,2250.31) 6165.22,2247.66 6263.25,2247.66 U16_A.2@6265.9,2245 U16_A.1@6265.9,2195 6363.78,2195 C39_A.2@6373.78,2185
  Bottom w10: R77_A.1@6118.74,2259.28 6119.46,2260 6147.46,2260 6157.15,2250.31 v1(6162.56,2250.31)
NetC39_B_1: C39_B.1 R79_B.2 R80_B.1 | length 228.5
  Top w10: v1@6420.12,5100.12 6440.35,5120.35 6440.35,5145.86 C39_B.1@6454.49,5160
  Bottom w10: v1(6420,5100) 6420,5159.06 R80_B.1@6419.06,5160 6428.74,5169.68 R79_B.2@6428.74,5250
NetC39_B_2: C39_B.2 R77_B.1 U16_B.1 U16_B.2 | length 315.7
  Top w10: v1(6162.56,5225.31) 6165.22,5222.66 6263.25,5222.66 U16_B.2@6265.9,5220 U16_B.1@6265.9,5170 6363.78,5170 C39_B.2@6373.78,5160
  Bottom w10: R77_B.1@6118.74,5234.28 6119.46,5235 6147.46,5235 6157.15,5225.31 v1(6162.56,5225.31)
NetC39_C_1: C39_C.1 R79_C.2 R80_C.1 | length 275.6
  Top w10: v1(6420,8074.51) 6420.12,8074.63 6420.12,8109.12 6420.12,8135.47 C39_C.1@6444.65,8160
  Bottom w10: v1(6420,8074.51) 6420,8159.06 6419.06,8160 6428.74,8169.68 R79_C.2@6428.74,8250
NetC39_C_2: C39_C.2 R77_C.1 U16_C.1 U16_C.2 | length 316.6
  Top w10: v1(6162.56,8225.31) 6165.22,8222.66 6263.25,8222.66 U16_C.2@6265.9,8220 U16_C.1@6265.9,8170 6363.78,8170 C39_C.2@6373.78,8160
  Bottom w10: R77_C.1@6118.74,8234.28 6120.53,8236.07 6147.46,8236.07 6158.22,8225.31 v1(6162.56,8225.31)
NetC39_D_1: C39_D.1 R79_D.2 R80_D.1 | length 224.6
  Top w10: v1(6445,11040) 6445.12,11040.12 6445.12,11075.47 C39_D.1@6469.65,11100
  Bottom w10: v1(6445,11040) 6445,11099.06 R80_D.1@6444.06,11100 6453.74,11109.68 R79_D.2@6453.74,11190
NetC39_D_2: C39_D.2 R77_D.1 U16_D.1 U16_D.2 | length 315.7
  Top w10: v1(6187.56,11165.31) 6190.22,11162.66 6288.25,11162.66 U16_D.2@6290.9,11160 U16_D.1@6290.9,11110 6388.78,11110 C39_D.2@6398.78,11100
  Bottom w10: R77_D.1@6143.74,11174.28 6144.46,11175 6172.46,11175 6182.15,11165.31 v1(6187.56,11165.31)
NetC40_A_2: C40_A.2 R80_A.2 U16_A.3 | length 208
  Top w10: U16_A.3@6265.9,2295 6329.68,2295 6333.54,2291.14 6334.53,2291.14 6350,2275.67 6350,2275.27 6328.39,2253.67 6328.39,2240.01 v1(6324.57,2236.18)
  Bottom w10: v1(6324.57,2236.18) 6328.39,2232.36 6328.39,2220.54 6349.25,2199.69 6349.25,2195.75 R80_A.2@6360,2185
NetC40_B_2: C40_B.2 R80_B.2 U16_B.3 | length 211.6
  Top w10: U16_B.3@6265.9,5270 6329.68,5270 6333.54,5266.14 6334.53,5266.14 6350,5250.67 6350,5250.27 6322.51,5222.78 6322.51,5201.82 v1(6321.45,5200.77)
  Bottom w10: v1(6321.45,5200.77) 6323.17,5200.77 6360,5163.94 R80_B.2@6360,5160
NetC40_C_2: C40_C.2 R80_C.2 U16_C.3 | length 210
  Top w10: U16_C.3@6265.9,8270 6329.68,8270 6333.54,8266.14 6334.53,8266.14 6350,8250.67 6350,8250.27 6323.21,8223.49 6323.21,8203.55 v1(6322.51,8202.84)
  Bottom w10: v1(6322.51,8202.84) 6326.33,8199.02 6326.33,8193.08 6359.41,8160 R80_C.2@6360,8160
NetC40_D_2: C40_D.2 R80_D.2 U16_D.3 | length 228.1
  Top w10: U16_D.3@6290.9,11210 6354.68,11210 6358.54,11206.14 6359.53,11206.14 C40_D.2@6375,11190.67 ; v1(6349.57,11151.18) 6352.13,11153.74 6368.35,11153.74 6374.21,11159.6 C40_D.2@6374.21,11190.47
  Bottom w10: v1(6349.57,11151.18) 6353.39,11147.36 6372.33,11147.36 6385,11134.69 R80_D.2@6385,11100
NetC41_A_2: C41_A.2 R78_A.2 U16_A.5 | length 191.5
  Top w10: U16_A.5@6059.21,2345 6060,2345.79 v1(6060,2400)
  Bottom w10: C41_A.2@5987.75,2324.52 5987.75,2325.51 6002.43,2340.2 6003.42,2340.2 6008.22,2345 R78_A.2@6059.68,2345 6060,2345.32 v1(6060,2400)
NetC41_B_2: C41_B.2 R78_B.2 U16_B.5 | length 191.5
  Top w10: U16_B.5@6059.21,5320 6060,5320.79 v1(6060,5375)
  Bottom w10: C41_B.2@5987.75,5299.53 5987.75,5300.51 6002.43,5315.2 6003.42,5315.2 6008.22,5320 R78_B.2@6059.68,5320 6060,5320.32 v1(6060,5375)
NetC41_C_2: C41_C.2 R78_C.2 U16_C.5 | length 191.5
  Top w10: U16_C.5@6059.21,8320 6060,8320.79 v1(6060,8375)
  Bottom w10: C41_C.2@5987.75,8299.53 5987.75,8300.51 6002.43,8315.2 6003.42,8315.2 6008.22,8320 R78_C.2@6059.68,8320 6060,8320.32 v1(6060,8375)
NetC41_D_2: C41_D.2 R78_D.2 U16_D.5 | length 191.5
  Top w10: U16_D.5@6084.21,11260 6085,11260.79 v1(6085,11315)
  Bottom w10: C41_D.2@6012.75,11239.53 6012.75,11240.51 6027.43,11255.2 6028.42,11255.2 6033.22,11260 R78_D.2@6084.68,11260 6085,11260.32 v1(6085,11315)
NetC43_1: C43.1 R81.1
NetC44_1: C44.1 R82.1
NetC46_2: C46.2 L2.2 R82.2 U17.1
NetC53_1: C53.1 R85.1
NetC54_1: C54.1 R86.1
NetC56_2: C56.2 L4.2 R86.2 U19.1
NetC59_A_1: C59_A.1 Q3_A.D U4_A.3 U4_A.4 | length 595.8
  Top w50: C59_A.1@9854.72,2775 9854.72,2250.28 Q3_A.D@9905,2200
NetC59_A_2: C59_A.2 R104_A.1 | length 230.8
  Top w50: C59_A.2@10445.28,2775 10452.77,2767.51 10507.49,2767.51 10568.9,2706.1 10615.35,2706.1 10617.91,2703.54 R104_A.1@10617.91,2675
NetC59_B_1: C59_B.1 Q3_B.D U4_B.3 U4_B.4 | length 570.8
  Top w50: C59_B.1@9854.72,5750 9854.72,5250.28 Q3_B.D@9905,5200
NetC59_B_2: C59_B.2 R104_B.1 | length 220.4
  Top w50: C59_B.2@10445.28,5750 10525,5750 10568.9,5706.1 10615.35,5706.1 10617.91,5703.54 R104_B.1@10617.91,5675
NetC59_C_1: C59_C.1 Q3_C.D U4_C.3 U4_C.4 | length 570.8
  Top w50: C59_C.1@9854.72,8750 9854.72,8250.28 Q3_C.D@9905,8200
NetC59_C_2: C59_C.2 R104_C.1 | length 215.9
  Top w50: C59_C.2@10445.28,8750 10452.77,8742.51 10507.49,8742.51 10551.59,8698.41 10615.35,8698.41 10617.91,8695.85 R104_C.1@10617.91,8675
NetC59_D_1: C59_D.1 Q3_D.D U4_D.3 U4_D.4 | length 595.8
  Top w50: C59_D.1@9854.72,11775 9854.72,11250.28 Q3_D.D@9905,11200
NetC59_D_2: C59_D.2 R104_D.1 | length 230.8
  Top w50: C59_D.2@10445.28,11775 10452.77,11767.51 10507.49,11767.51 10568.9,11706.1 10615.35,11706.1 10617.91,11703.54 R104_D.1@10617.91,11675
NetD5_A_2: D5_A.2 R67_A.2 | length 344.8
  Top w10: D5_A.2@6024.88,1305 6026.17,1305 6032,1299.17 6032,1268.86 6037.86,1263 6283,1263 6300,1280 R67_A.2@6300,1307.44
NetD5_B_2: D5_B.2 R67_B.2 | length 344.8
  Top w10: D5_B.2@6024.88,4305 6026.17,4305 6032,4299.17 6032,4268.86 6037.86,4263 6283,4263 6300,4280 R67_B.2@6300,4307.44
NetD5_C_2: D5_C.2 R67_C.2 | length 344.8
  Top w10: D5_C.2@5999.88,7130 6001.17,7130 6007,7124.17 6007,7093.86 6012.86,7088 6258,7088 6275,7105 R67_C.2@6275,7132.44
NetD5_D_2: D5_D.2 R67_D.2 | length 344.8
  Top w10: D5_D.2@6024.88,10255 6026.17,10255 6032,10249.17 6032,10218.86 6037.86,10213 6283,10213 6300,10230 R67_D.2@6300,10257.44
NetD5_E_2: D5_E.2 R67_E.2 | length 344.8
  Top w10: D5_E.2@4164.88,10880 4166.17,10880 4172,10874.17 4172,10843.86 4177.86,10838 4423,10838 4440,10855 R67_E.2@4440,10882.44
NetD6_A_1: D6_A.1 Q3_A.G R89_A.2 R91_A.2 | length 1284.9
  Top w30: R89_A.2@9750,1008.39 R91_A.2@9850,1008.39 ; Q3_A.G@9905,1700 9905,1624.65 10135.63,1394.02 D6_A.1@10135.63,1325
  Top w50: R91_A.2@9850,1008.39 9850,1645 Q3_A.G@9905,1700
NetD6_B_1: D6_B.1 Q3_B.G R89_B.2 R91_B.2 | length 1284.9
  Top w30: R89_B.2@9750,4008.39 R91_B.2@9850,4008.39 ; Q3_B.G@9905,4700 9905,4624.65 10135.63,4394.02 D6_B.1@10135.63,4325
  Top w50: R91_B.2@9850,4008.39 9850,4645 Q3_B.G@9905,4700
NetD6_C_1: D6_C.1 Q3_C.G R89_C.2 R91_C.2 | length 1284.9
  Top w30: R89_C.2@9750,7008.39 R91_C.2@9850,7008.39 ; Q3_C.G@9905,7700 9905,7624.65 10135.63,7394.02 D6_C.1@10135.63,7325
  Top w50: R91_C.2@9850,7008.39 9850,7645 Q3_C.G@9905,7700
NetD6_D_1: D6_D.1 Q3_D.G R89_D.2 R91_D.2 | length 1299.1
  Top w15: Q3_D.G@9895,10690 Q3_D.G@9905,10700
  Top w30: R89_D.2@9750,10008.39 R91_D.2@9850,10008.39 ; Q3_D.G@9905,10700 9905,10624.65 10135.63,10394.02 D6_D.1@10135.63,10325
  Top w50: R91_D.2@9850,10008.39 9850,10645 Q3_D.G@9905,10700
NetD7_A_1: D7_A.1 R89_A.1 | length 92.9
  Top w25: D7_A.1@9739.76,845 9743.21,845 9744.88,846.67 9744.88,926.5 R89_A.1@9750,931.61
NetD7_B_1: D7_B.1 R89_B.1 | length 76.5
  Top w25: D7_B.1@9744.88,3850 R89_B.1@9744.88,3926.5
NetD7_C_1: D7_C.1 R89_C.1 | length 101.6
  Top w25: D7_C.1@9750,6830 R89_C.1@9750,6931.61
NetD7_D_1: D7_D.1 R89_D.1 | length 101.6
  Top w25: D7_D.1@9750,9830 R89_D.1@9750,9931.61
NetFB1_2: FB1.2 MH8.1
NetFB2_2: FB2.2 MH11.1
NetJ4_A: D1_A.4 J4.A K1_A.3
  other v1: 13150,1100 13150,1200 13550,1200 13150,1300 13550,1300
NetJ4_B: D1_A.1 D1_A.3 J4.B K2_A.3
NetJ5_A: D1_B.4 J5.A K1_B.3
  other v1: 13150,4100 13150,4200 13550,4200 13150,4300 13550,4300
NetJ5_B: D1_B.1 D1_B.3 J5.B K2_B.3
NetJ6_A: D1_C.4 J6.A K1_C.3
  other v1: 13150,7100 13150,7200 13550,7200 13150,7300 13550,7300
NetJ6_B: D1_C.1 D1_C.3 J6.B K2_C.3
NetJ7_A: D1_D.4 J7.A K1_D.3
  other v1: 13150,10100 13150,10200 13550,10200 13150,10300 13550,10300
NetJ7_B: D1_D.1 D1_D.3 J7.B K2_D.3
NetK1_A_1: D8_A.2 K1_A.1 R99_A.1 R102_A.2 U18_A.7 | length 771.6
  Top w12: U18_A.7@10725.2,650 10800,650 10835.24,685.24 D8_A.2@10835.24,750 10835.24,1030.24 10855,1050 R102_A.2@10913.98,1050
  Bottom w15: K1_A.1@12800,1110 R99_A.1@12800,1325
NetK1_B_1: D8_B.2 K1_B.1 R99_B.1 R102_B.2 U18_B.7 | length 771.6
  Top w12: U18_B.7@10725.2,3650.2 10800,3650.2 10835.24,3685.43 D8_B.2@10835.24,3750.2 10835.24,4030.43 10855,4050.2 R102_B.2@10913.98,4050.2
  Bottom w15: K1_B.1@12800,4110 R99_B.1@12800,4325
NetK1_C_1: D8_C.2 K1_C.1 R99_C.1 R102_C.2 U18_C.7 | length 771.6
  Top w12: U18_C.7@10725.2,6650.2 10800,6650.2 10835.24,6685.43 D8_C.2@10835.24,6750.2 10835.24,7030.43 10855,7050.2 R102_C.2@10913.98,7050.2
  Bottom w15: K1_C.1@12800,7110 R99_C.1@12800,7325
NetK1_D_1: D8_D.2 K1_D.1 R99_D.1 R102_D.2 U18_D.7 | length 771.6
  Top w12: U18_D.7@10725.2,9650.2 10800,9650.2 10835.24,9685.43 10835.24,9750.2 10835.24,10030.43 10855,10050.2 R102_D.2@10913.98,10050.2
  Bottom w15: K1_D.1@12800,10110 R99_D.1@12800,10325
NetQ2_A_1: Q2_A.1 R64_A.2 R65_A.2 | length 260
  Top w10: Q2_A.1@7225.68,2288.34 7225.68,2249.32 7244.8,2230.2 R65_A.2@7340,2230.2 ; R65_A.2@7339.25,2230.94 7339.72,2230.47 R65_A.2@7340,2230.2 ; R64_A.2@7340,2132.56 R65_A.2@7340,2230.2
NetQ2_B_1: Q2_B.1 R64_B.2 R65_B.2 | length 260
  Top w10: Q2_B.1@7575.68,2288.34 7575.68,2249.32 7594.8,2230.2 R65_B.2@7690,2230.2 ; R65_B.2@7689.25,2230.94 7689.72,2230.47 R65_B.2@7690,2230.2 ; R64_B.2@7690,2132.56 R65_B.2@7690,2230.2
NetQ2_C_1: Q2_C.1 R64_C.2 R65_C.2 | length 260
  Top w10: Q2_C.1@7225.68,5288.34 7225.68,5249.32 7244.8,5230.2 R65_C.2@7340,5230.2 ; R65_C.2@7339.25,5230.94 7339.72,5230.47 R65_C.2@7340,5230.2 ; R64_C.2@7340,5132.56 R65_C.2@7340,5230.2
NetQ2_D_1: Q2_D.1 R64_D.2 R65_D.2 | length 260
  Top w10: Q2_D.1@7575.68,5288.34 7575.68,5249.32 7594.8,5230.2 R65_D.2@7690,5230.2 ; R65_D.2@7689.25,5230.94 7689.72,5230.47 R65_D.2@7690,5230.2 ; R64_D.2@7690,5132.56 R65_D.2@7690,5230.2
NetQ2_E_1: Q2_E.1 R64_E.2 R65_E.2 | length 260
  Top w10: Q2_E.1@7225.68,8288.34 7225.68,8249.32 7244.8,8230.2 R65_E.2@7340,8230.2 ; R65_E.2@7339.25,8230.94 7339.72,8230.47 R65_E.2@7340,8230.2 ; R64_E.2@7340,8132.56 R65_E.2@7340,8230.2
NetQ2_F_1: Q2_F.1 R64_F.2 R65_F.2 | length 260
  Top w10: Q2_F.1@7575.68,8288.34 7575.68,8249.32 7594.8,8230.2 R65_F.2@7690,8230.2 ; R65_F.2@7689.25,8230.94 7689.72,8230.47 R65_F.2@7690,8230.2 ; R64_F.2@7690,8132.56 R65_F.2@7690,8230.2
NetQ2_G_1: Q2_G.1 R64_G.2 R65_G.2 | length 261.2
  Top w10: Q2_G.1@7224.06,11289.96 7225.68,11288.34 7225.68,11249.32 7244.8,11230.2 7340,11230.2 R64_G.2@7340,11132.56
NetQ2_H_1: Q2_H.1 R64_H.2 R65_H.2 | length 260
  Top w10: Q2_H.1@7575.68,11288.34 7575.68,11249.32 7594.8,11230.2 R65_H.2@7690,11230.2 ; R65_H.2@7689.25,11230.94 7689.72,11230.47 R65_H.2@7690,11230.2 ; R64_H.2@7690,11132.56 R65_H.2@7690,11230.2
NetQ4_A_1: Q4_A.1 R63_A.2 | length 87.6
  Top w10: R63_A.2@8013.39,1250 Q4_A.1@8100.98,1250
NetQ4_B_1: Q4_B.1 R63_B.2 | length 162.6
  Top w10: R63_B.2@7938.39,4325 Q4_B.1@8100.98,4325
NetQ4_C_1: Q4_C.1 R63_C.2 | length 124.2
  Top w10: R63_C.2@7976.77,7325 Q4_C.1@8100.98,7325
NetQ4_D_1: Q4_D.1 R63_D.2 | length 116
  Top w10: R63_D.2@7985,10325 Q4_D.1@8100.98,10325
NetQ5_A_1: Q5_A.1 R84_A.2 | length 99.2
  Top w20: Q5_A.1@8932.4,676.18 8932.89,676.67 8932.89,774.51 R84_A.2@8933.39,775
NetQ5_A_3: Q5_A.3 R76_A.1 | length 150.2
  Top w20: Q5_A.3@8895,573.82 8895.3,573.52 9044.7,573.52 R76_A.1@9045,573.23
NetQ5_B_1: Q5_B.1 R84_B.2 | length 97.8
  Top w20: Q5_B.1@8923.15,3660.83 R84_B.2@8923.15,3758.66
NetQ5_B_3: Q5_B.3 R76_B.1 | length 150.2
  Top w20: Q5_B.3@8893.42,3557.48 8893.72,3557.19 9043.13,3557.19 R76_B.1@9043.42,3556.89
NetQ5_C_1: Q5_C.1 R84_C.2 | length 97.8
  Top w20: Q5_C.1@8930.83,6659.84 R84_C.2@8930.83,6757.68
NetQ5_C_3: Q5_C.3 R76_C.1 | length 150.2
  Top w20: Q5_C.3@8893.42,6557.48 8893.72,6557.19 9043.13,6557.19 R76_C.1@9043.42,6556.89
NetQ5_D_1: Q5_D.1 R84_D.2 | length 97.8
  Top w20: Q5_D.1@8930.83,9659.84 R84_D.2@8930.83,9757.68
NetQ5_D_3: Q5_D.3 R76_D.1 | length 150.2
  Top w20: Q5_D.3@8893.42,9557.48 8893.72,9557.19 9043.13,9557.19 R76_D.1@9043.42,9556.89
NetQ6_A_3: Q6_A.3 R76_A.2 U6_A.1 | length 313.3
  Top w20: R76_A.2@9045,650 U6_A.1@9166.34,650 9185.25,650 9187.84,652.58 9187.84,694.25 9225,731.42 Q6_A.3@9225,806.6
NetQ6_B_3: Q6_B.3 R76_B.2 U6_B.1 | length 313.3
  Top w20: R76_B.2@9043.42,3633.66 U6_B.1@9164.76,3633.66 9183.68,3633.66 9186.26,3636.24 9186.26,3677.91 9223.42,3715.08 Q6_B.3@9223.42,3790.26
NetQ6_C_3: Q6_C.3 R76_C.2 U6_C.1 | length 306.9
  Top w20: R76_C.2@9043.42,6633.66 U6_C.1@9164.76,6633.66 9183.68,6633.66 9186.26,6636.24 9186.26,6677.91 9225,6716.65 Q6_C.3@9225,6783.17
NetQ6_D_3: Q6_D.3 R76_D.2 U6_D.1 | length 306.9
  Top w20: R76_D.2@9043.42,9633.66 U6_D.1@9164.76,9633.66 9183.68,9633.66 9186.26,9636.24 9186.26,9677.91 9225,9716.65 Q6_D.3@9225,9783.17
NetQ7_A_1: Q7_A.1 R92_A.2 | length 99.2
  Top w15: Q7_A.1@8946.18,862.6 9044.02,862.6 R92_A.2@9045,861.61
NetQ7_A_3: Q7_A.3 R84_A.1 U21_A.2 | length 243.6
  Top w15: U21_A.2@8730.47,900 Q7_A.3@8843.82,900 8843.82,787.8 R84_A.1@8856.61,775
NetQ7_B_1: Q7_B.1 R92_B.2 | length 99.2
  Top w15: Q7_B.1@8944.6,3846.26 9042.44,3846.26 R92_B.2@9043.42,3845.28
NetQ7_B_3: Q7_B.3 R84_B.1 U21_B.2 | length 243.6
  Top w15: U21_B.2@8728.9,3883.66 8842.24,3883.66 8842.24,3771.46 R84_B.1@8855.04,3758.66
NetQ7_C_1: Q7_C.1 R92_C.2 | length 99.2
  Top w15: Q7_C.1@8944.6,6846.26 9042.44,6846.26 R92_C.2@9043.42,6845.28
NetQ7_C_3: Q7_C.3 R84_C.1 U21_C.2 | length 243.6
  Top w15: U21_C.2@8728.9,6883.66 Q7_C.3@8842.24,6883.66 8842.24,6771.46 R84_C.1@8855.04,6758.66
NetQ7_D_1: Q7_D.1 R92_D.2 | length 99.2
  Top w15: Q7_D.1@8944.6,9846.26 9042.44,9846.26 R92_D.2@9043.42,9845.28
NetQ7_D_3: Q7_D.3 R84_D.1 U21_D.2 | length 243.6
  Top w15: U21_D.2@8728.9,9883.66 Q7_D.3@8842.24,9883.66 8842.24,9771.46 R84_D.1@8855.04,9758.66
NetQ8_A_1: Q8_A.1 R83_A.1 | length 101
  Top w20: Q8_A.1@8349.02,1500 R83_A.1@8450,1500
